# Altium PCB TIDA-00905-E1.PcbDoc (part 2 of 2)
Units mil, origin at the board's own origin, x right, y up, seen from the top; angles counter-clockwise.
Board outline 3740.15 x 5314.95 mil, 4 copper layers (Top Layer, GND, PWR, Bottom Layer), stack 79.834 mil thick; 196 components, 87 nets, 593 pads, 163 vias.
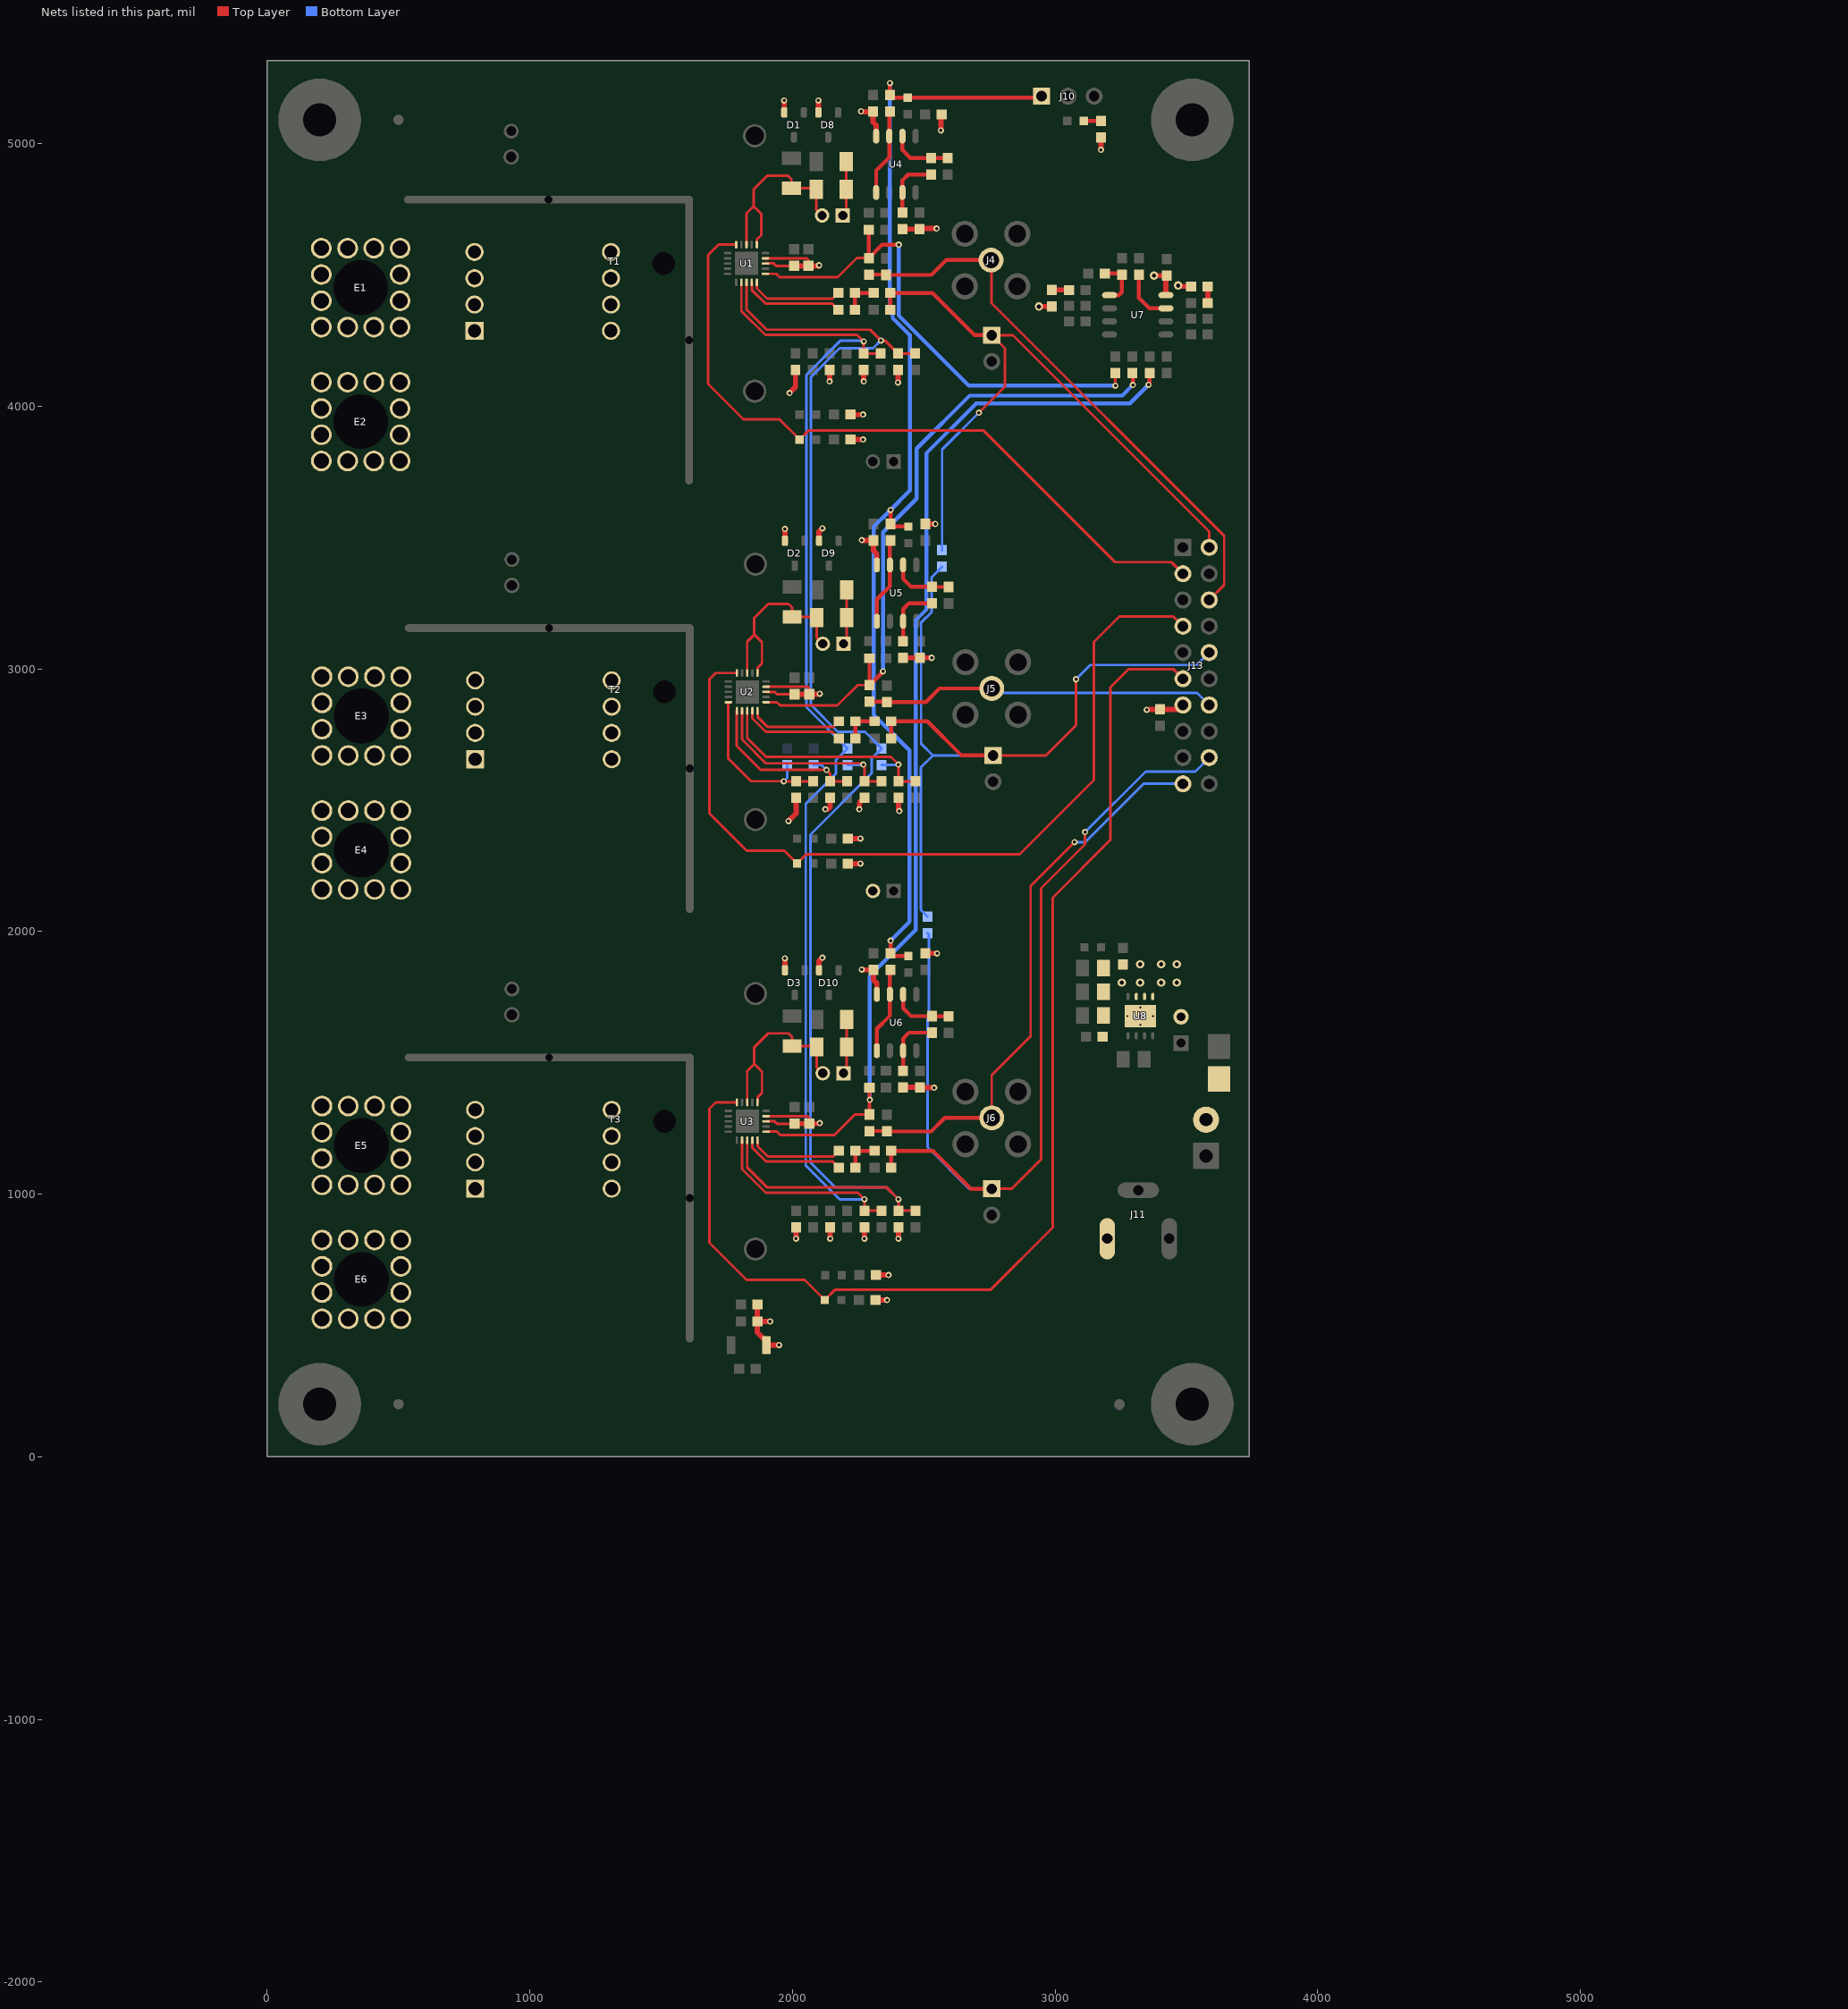
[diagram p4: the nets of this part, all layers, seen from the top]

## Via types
v1: diameter 24, hole 12, Top Layer to Bottom Layer, 127 vias
v2: diameter 32, hole 16, Top Layer to Bottom Layer, 19 vias
v3: diameter 19.68, hole 7.87, Top Layer to Bottom Layer, 17 vias

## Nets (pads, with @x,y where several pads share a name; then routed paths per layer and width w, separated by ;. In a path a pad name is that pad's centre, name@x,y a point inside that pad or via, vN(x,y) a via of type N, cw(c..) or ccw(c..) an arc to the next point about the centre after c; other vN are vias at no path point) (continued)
NetD17_2: D17.2 R82.1 | length 65.7
  Top Layer w15: D17.2@3109.5,5086 3110,5085.5 R82.1@3175,5085.5
NetD18_2: D18.2 J11.1 J14.2
NetE1_1: E1.1 T1.1 T1.2 T1.3 T1.4
NetE2_1: E2.1 T1.5 T1.6 T1.7 T1.8
NetE3_1: E3.1 T2.1 T2.2 T2.3 T2.4
NetE4_1: E4.1 T2.5 T2.6 T2.7 T2.8
NetE5_1: E5.1 T3.1 T3.2 T3.3 T3.4
NetE6_1: E6.1 T3.5 T3.6 T3.7 T3.8
NetJ1_1: J1.1 R12.2 R13.1 | length 210.3
  Top Layer w10: J1.1@2191.77,4726.11 2204.49,4738.83 R13.1@2204.49,4826.11 R12.2@2204.49,4931.11
NetJ1_2: J1.2 R3.2 R13.2 U1.11 U1.13 | length 797.9
  Top Layer w10: U1.13@1825.4,4614.96 1825.4,4734.11 1852.4,4761.11 ; U1.11@1864.77,4614.96 1864.77,4634.48 1881.4,4651.11 1881.4,4732.11 1852.4,4761.11 ; J1.2@2113.03,4726.11 2090.31,4748.83 R13.2@2090.31,4826.11 2087.4,4829.02 R3.2@1996.4,4829.02 1996.4,4864.11 1982.4,4878.11 1905.11,4878.11 1852.4,4825.4 1852.4,4761.11
NetJ2_1: J2.1 R14.2 R15.1 | length 210.3
  Top Layer w10: J2.1@2194.37,3095 2207.09,3107.72 R15.1@2207.09,3195 R14.2@2207.09,3300
NetJ2_2: J2.2 R4.2 R15.2 U2.11 U2.13 | length 797.9
  Top Layer w10: U2.13@1828,2983.85 1828,3103 1855,3130 ; U2.11@1867.37,2983.85 1867.37,3003.37 1884,3020 1884,3101 1855,3130 ; J2.2@2115.63,3095 2092.91,3117.72 R15.2@2092.91,3195 2090,3197.91 R4.2@1999,3197.91 1999,3233 1985,3247 1907.71,3247 1855,3194.29 1855,3130
NetJ3_1: J3.1 R16.2 R17.1 | length 210.3
  Top Layer w10: J3.1@2194.37,1460 2207.09,1472.72 R17.1@2207.09,1560 R16.2@2207.09,1665
NetJ3_2: J3.2 R5.2 R17.2 U3.11 U3.13 | length 797.9
  Top Layer w10: U3.13@1828,1348.85 1828,1468 1855,1495 ; U3.11@1867.37,1348.85 1867.37,1368.37 1884,1385 1884,1466 1855,1495 ; J3.2@2115.63,1460 2092.91,1482.72 R17.2@2092.91,1560 2090,1562.91 R5.2@1999,1562.91 1999,1598 1985,1612 1907.71,1612 1855,1559.29 1855,1495
NetR7_1: R7.1 R10.1 R91.2 U2.20 | length 640.2
  Top Layer w10: U2.20@1756.15,2872.63 1756.15,2657.85 1842.11,2571.89 v1@1966.6,2571.89 ; v1(1966.99,2571.5) R7.1@2014,2571.5 R10.1@2079,2571.5
  Bottom Layer w10: v1(1966.99,2571.5) 1980,2584.5 R91.2@1980,2633.5
NetR19_1: R19.1 R32.1 R90.2 U2.1 | length 685.6
  Top Layer w10: U2.1@1788.63,2840.15 1788.63,2705.37 1879,2615 v1(2130,2615) 2144,2601 R19.1@2144,2571.5 R32.1@2209,2571.5
  Bottom Layer w10: R90.2@2080,2633.5 2111.5,2633.5 v1(2130,2615)
NetR25_1: R25.1 U1.5 | length 360
  Top Layer w10: U1.5@1864.77,4471.26 1864.77,4448.2 1903.86,4409.11 2152.89,4409.11 R25.1@2174.89,4431.11 R25.1@2174.89,4429.6
NetR25_2: R25.2 R26.1 R45.1 | length 137
  Top Layer w15: R26.1@2237.9,4366.11 R25.2@2237.88,4431.11 R45.1@2309.91,4431.11
NetR26_2: R26.2 U1.4 | length 390.3
  Top Layer w10: U1.4@1845.09,4471.26 1845.09,4442.43 1896.4,4391.11 2149.91,4391.11 R26.2@2174.91,4366.11
NetR27_1: R27.1 U2.5 | length 360
  Top Layer w10: U2.5@1867.37,2840.15 1867.37,2817.09 1906.46,2778 2155.46,2778 R27.1@2177.46,2800 R27.1@2177.46,2798.49
NetR27_2: R27.2 R28.1 R46.1 | length 137
  Top Layer w15: R28.1@2240.47,2735 R27.2@2240.45,2800 R46.1@2312.48,2800
NetR28_2: R28.2 U2.4 | length 390.2
  Top Layer w10: U2.4@1847.68,2840.15 1847.68,2811.32 1899,2760 2152.48,2760 R28.2@2177.48,2735
NetR29_1: R29.1 U3.5 | length 360
  Top Layer w10: U3.5@1867.37,1205.15 1867.37,1182.09 1906.46,1143 2155.49,1143 R29.1@2177.49,1165 R29.1@2177.49,1163.49
NetR29_2: R29.2 R30.1 R47.1 | length 137
  Top Layer w15: R30.1@2240.5,1100 R29.2@2240.48,1165 R47.1@2312.5,1165
NetR30_2: R30.2 U3.4 | length 390.3
  Top Layer w10: U3.4@1847.68,1205.15 1847.68,1176.32 1899,1125 2152.5,1125 R30.2@2177.5,1100
NetR37_1: R37.1 R49.1 R89.2 U2.2 | length 810.3
  Top Layer w10: U2.2@1808.31,2840.15 1808.31,2730.69 1899,2640 v1@2270,2640 ; v1(2270,2635) v1@2270,2640 ; R49.1@2339,2571.5 R37.1@2274,2571.5 2274,2634 2275,2635 v1@2270,2640
  Bottom Layer w10: R89.2@2210,2633.5 2268.5,2633.5 v1(2270,2635)
NetR51_1: R51.1 U4.1 U4.7 | length 329.3
  Top Layer w15: U4.1@2319,4813.39 2319,4896.78 2369,4946.78 U4.7@2369,5027.95 2369,5118.5 R51.1@2371.48,5120.99
NetR52_1: R52.1 U5.1 U5.7 | length 329.3
  Top Layer w15: U5.1@2321.52,3180.91 2321.52,3264.3 2371.52,3314.3 U5.7@2371.52,3395.47 2371.52,3486.02 R52.1@2374,3488.5
NetR53_1: R53.1 U6.1 U6.7 | length 329.3
  Top Layer w15: U6.1@2321.52,1545.91 2321.52,1629.3 2371.52,1679.3 U6.7@2371.52,1760.47 2371.52,1851.02 R53.1@2374,1853.5
NetR55_1: R55.1 R61.1 R88.2 U2.3 | length 915.4
  Top Layer w10: U2.3@1828,2840.15 1828,2736.46 1899.46,2665 2375,2665 2404,2636 v1(2404,2635) R55.1@2404,2571.5 R61.1@2469,2571.5
  Bottom Layer w10: R88.2@2340,2633.5 2402.5,2633.5 v1(2404,2635)
NetR57_1: R57.1 R66.2 U4.3 | length 241.7
  Top Layer w15: R57.1@2419,4737.17 U4.3@2419,4813.39 2419,4860 2440.99,4881.99 R66.2@2528.75,4881.99
NetR58_1: R58.1 R67.2 U5.3 | length 241.7
  Top Layer w15: R58.1@2421.52,3104.69 U5.3@2421.52,3180.91 2421.52,3227.52 2443.51,3249.5 R67.2@2531.27,3249.5
NetR59_1: R59.1 R68.2 U6.3 | length 241.7
  Top Layer w15: R59.1@2421.52,1469.69 U6.3@2421.52,1545.91 2421.52,1592.52 2443.51,1614.5 R68.2@2531.27,1614.5
NetR66_1: R66.1 R69.2 U4.6 | length 238.3
  Top Layer w15: U4.6@2419,5027.95 2419,4974.96 2448.98,4944.98 R66.1@2528.75,4944.98 2529.75,4943.98 R69.2@2591.48,4943.98
NetR67_1: R67.1 R70.2 U5.6 | length 238.3
  Top Layer w15: U5.6@2421.52,3395.47 2421.52,3342.48 2451.5,3312.5 R67.1@2531.27,3312.5 2532.27,3311.5 R70.2@2594,3311.5
NetR68_1: R68.1 R71.2 U6.6 | length 238.3
  Top Layer w15: U6.6@2421.52,1760.47 2421.52,1707.48 2451.5,1677.5 R68.1@2531.27,1677.5 2532.27,1676.5 R71.2@2594,1676.5
NetR72_2: R72.2 R73.1 | length 65.8
  Top Layer w20: R72.2@2987.66,4442.5 R73.1@3053.47,4442.48
NetR75_2: R75.2 R78.1 U7.1 | length 189.4
  Top Layer w15: R75.2@3184.43,4499.98 R75.2@3189.16,4499.98 ; R75.2@3189.16,4505 3249.41,4505 R78.1@3254.43,4499.98 3254.43,4434.24 3242.66,4422.48 U7.1@3207.68,4422.48
NetR80_1: R80.1 U7.7 | length 207
  Top Layer w15: R80.1@3319.43,4499.98 3319.43,4412.24 3359.18,4372.48 U7.7@3422.25,4372.48
NetR83_2: R83.2 R84.1 | length 63.6
  Top Layer w20: R84.1@3581.46,4392.48 R83.2@3581.5,4456
OC_FAULT: D13.1 D14.1 D15.1 J10.1 R51.2 R52.2 R53.2 | length 4314.5
  Top Layer w15: v1(2371.48,5230) R51.2@2371.48,5183.98 2381.48,5173.98 D13.1@2438.92,5173.98 2942.98,5173.98 J10.1@2949,5180 ; v1(2374,1965) R53.2@2374,1916.5 2384,1906.5 D15.1@2441.44,1906.5 ; v1(2374,3605) R52.2@2374,3551.5 2384,3541.5 D14.1@2441.44,3541.5
  Bottom Layer w15: v1(2371.48,5230) 2371.48,4358 2382,4347.48 2382,4335.47 2447,4270.47 2447,3678 v1(2374,3605) 2310,3541 2310,2825 2446,2689 2446,2037 v1(2374,1965)
OR-U: D11.1 J13.11 U3.15 | length 4604.6
  Top Layer w10: U3.15@1788.63,1348.85 1707.85,1348.85 1684,1325 1684,815 1825.54,673.46 2046.53,673.46 D11.1@2123.53,596.46 2163.53,636.46 2755.46,636.46 2991,872 2991,2129 3211,2349 3211,2929 3281,2999 3450,2999 J13.11@3487,2962
OR-V: D5.1 J13.7 U2.15 | length 3219.8
  Top Layer w10: U2.15@1788.63,2983.85 1707.85,2983.85 1684,2960 1684,2449.54 1826.54,2307 1969.05,2307 D5.1@2017.5,2258.54 2052.5,2293.54 2865,2293.54 3148,2576.54 3148,3102 3245,3199 3450,3199 J13.7@3487,3162
OR-W: D7.1 J13.3 U1.15 | length 2750.3
  Top Layer w10: U1.15@1786.03,4614.96 1718.96,4614.96 1679,4575 1679,4084.54 1813.81,3949.73 1950.48,3949.73 D7.1@2027.48,3872.73 2062.48,3907.73 2726.81,3907.73 3228.54,3406 3443,3406 J13.3@3487,3362
REFOUT-U: C16.1 J8.1 J13.18 R47.2 R87.1 | length 3776.9
  Top Layer w10: J8.1@2759,1020 2835,1020 2947,1132 2947,2164 3114,2331 v1(3114,2378)
  Top Layer w15: C16.1@2375.5,1100 R47.2@2375.5,1165 2535,1165 2680,1020 J8.1@2759,1020
  Bottom Layer w10: R87.1@2515,1993.5 2519.52,1988.98 2519.52,1686.64 2515,1682.12 2515,1179 2674,1020 J8.1@2759,1020 ; v1(3114,2378) 3345,2609 3534,2609 J13.18@3587,2662
REFOUT-V: C15.1 J9.1 J13.10 R46.2 R86.1 R87.2 | length 3237.5
  Top Layer w10: J9.1@2764,2670 2965,2670 3080,2785 v1(3080,2960)
  Top Layer w15: C15.1@2375.47,2735 R46.2@2375.47,2800 2514,2800 2644,2670 J9.1@2764,2670
  Bottom Layer w10: R87.2@2515,2056.5 2489.5,2082 2489.5,2624.5 2535,2670 ; R86.1@2570,3388.5 2530.5,3349 2530.5,3216.51 2490,3176.01 2490,2715 2535,2670 ; J9.1@2764,2670 2535,2670 ; v1(3080,2960) 3134.52,3014.52 3539.52,3014.52 J13.10@3587,3062
REFOUT-W: C12.1 J7.1 J13.2 R45.2 R86.2 | length 2654.5
  Top Layer w10: v1(2710,3975) 2809,4074 2809,4220 J7.1@2759,4270 2840,4270 3587,3523 J13.2@3587,3462
  Top Layer w15: C12.1@2372.9,4366.11 R45.2@2372.9,4431.11 2532.89,4431.11 2694,4270 J7.1@2759,4270
  Bottom Layer w10: R86.2@2570,3451.5 2570,3835 v1(2710,3975)
RSEL0: R54.1 R56.1 R60.1 R62.1 R88.1 U1.3 U3.3 | length 5644.7
  Top Layer w10: U1.3@1825.4,4471.26 1825.4,4367.57 1901.86,4291.11 2295.89,4291.11 v1(2337,4250) 2352.23,4250 R54.1@2401.73,4200.5 R60.1@2466.73,4200.5 ; U3.3@1828,1205.15 1828,1101.46 1904.46,1025 2359,1025 v1(2404,980) R56.1@2404,936.5 R62.1@2469,936.5
  Bottom Layer w10: v1(2337,4250) 2307,4220 2179.46,4220 2071,4111.54 2071,2861.98 2172.98,2760 2276.5,2760 R88.1@2340,2696.5 2301.27,2657.76 2301.27,2601.27 2069,2369 2069,1120.46 2164.46,1025 2359,1025 v1(2404,980)
RSEL1: R36.1 R38.1 R48.1 R50.1 R89.1 U1.2 U3.2 | length 5158.7
  Top Layer w10: U1.2@1805.72,4471.26 1805.72,4361.8 1896.4,4271.11 2246.4,4271.11 v1(2271.4,4246.11) R36.1@2271.4,4202.61 ; U3.2@1808.31,1205.15 1808.31,1095.69 1899,1005 2249,1005 v1(2274,980) R38.1@2274,936.5 ; R36.1@2270.24,4200.5 R36.1@2271.73,4200.5 R48.1@2336.73,4200.5 ; R38.1@2272.5,936.5 R38.1@2274,936.5 ; R50.1@2339,936.5 R38.1@2274,936.5
  Bottom Layer w10: v1(2274,980) 2180,980 2051,1109 2051,2486 2166,2601 2166,2652.5 R89.1@2210,2696.5 2053,2853.5 2053,4119 2184,4250 v1@2274,4250
VDD: C1.1 C2.1 C3.1 C4.1 C5.1 C6.1 C7.1 C11.1 C13.1 C14.1 C20.1 C21.1 C22.1 C24.2 C25.1 C26.1 C27.1 C28.2 C30.1 D1.2 D2.2 D3.2 D8.2 D9.2 D10.2 J12.2 J13.13 J15.2 R2.2 R6.2 R7.2 R8.2 R18.2 R19.2 R20.2 R21.2 R22.2 R23.2 R24.2 R34.2 R35.2 R36.2 R37.2 R38.2 R54.2 R55.2 R56.2 R57.2 R58.2 R59.2 R63.2 R64.2 R65.2 R72.1 R76.2 R82.2 R83.1 S1.1 U1.8 U1.9 U2.8 U2.9 U3.8 U3.9 U4.8 U5.8 U6.8 U7.8 U8.5 U8.6 U8.7 U8.9 | length 4047.4
  Top Layer w10: U1.8@1897.25,4543.11 1929.4,4543.11 1938.45,4534.06 C2.1@2006.4,4534.06 ; U1.9@1897.25,4562.8 2055,4562.8 2061,4556.8 2061,4534.46 C5.1@2061.4,4534.06 ; U3.8@1899.85,1277 1932,1277 1941.05,1267.95 C4.1@2009,1267.95 ; U3.9@1899.85,1296.69 2057.6,1296.69 2063.6,1290.69 2063.6,1268.35 C7.1@2064,1267.95 ; U2.8@1899.85,2912 1932,2912 1941.05,2902.95 C3.1@2009,2902.95 ; U2.9@1899.85,2931.69 2057.6,2931.69 2063.6,2925.69 2063.6,2903.35 C6.1@2064,2902.95
  Top Layer w20: R2.2@1866.5,580 C1.1@1866.5,515 ; v1(1915,515) C1.1@1866.5,515 ; v1(1949.43,425) S1.1@1900.93,425 1900.93,439.07 1866.5,473.5 C1.1@1866.5,515 ; D1.2@1969,5118.35 v1(1969,5163.51) ; D3.2@1971.6,1852.24 v1(1971.6,1897.4) ; D2.2@1971.6,3487.24 v1(1971.6,3532.4) ; v1(1985,2420) 2014,2449 R7.2@2014,2508.5 ; v1(1989,4050) 2011.73,4072.73 R6.2@2011.73,4137.5 ; C2.1@2006.4,4534.06 C5.1@2061.4,4534.06 2099.36,4534.06 v1(2101.4,4536.11) ; C4.1@2009,1267.95 C7.1@2064,1267.95 2101.95,1267.95 v1(2104,1270) ; C3.1@2009,2902.95 C6.1@2064,2902.95 2101.95,2902.95 v1(2104,2905) ; v1(2014,830) R8.2@2014,873.5 ; D8.2@2099,5118.35 v1(2099,5163.51) ; D10.2@2101.6,1852.24 2101.6,1887.6 v1(2114,1900) ; D9.2@2101.6,3487.24 2101.6,3522.6 v1(2114,3535) ; v1(2125,2465) 2135,2465 2144,2474 R19.2@2144,2508.5 ; v1(2141.73,4094) R18.2@2141.73,4137.5 ; v1(2144,830) R20.2@2144,873.5 ; R22.2@2210.5,2258.54 v1(2259,2258.54) ; R21.2@2210.5,2353.54 v1(2259,2353.54) ; R24.2@2220.47,3872.73 v1(2268.98,3872.73) ; R23.2@2220.47,3967.73 v1(2268.98,3967.73) ; v1(2255,2465) 2255,2490 ; R37.2@2255.5,2490 R37.2@2274,2508.5 ; v1(2261.48,5122.48) 2262.98,5120.99 C11.1@2306.48,5120.99 2306.48,5082.48 2319,5069.96 U4.8@2319,5027.95 ; v1(2264,1855) 2265.5,1853.5 C14.1@2309,1853.5 2309,1815 2321.52,1802.48 U6.8@2321.52,1760.47 ; v1(2264,3490) 2265.5,3488.5 C13.1@2309,3488.5 2309,3450 2321.52,3437.48 U5.8@2321.52,3395.47 ; v1(2271.73,4094) R36.2@2271.73,4137.5 ; v1(2274,830) R38.2@2274,873.5 ; R34.2@2316.52,596.46 v1(2360.02,596.46) ; R35.2@2318.02,691.46 v1(2366.52,691.46) ; v1(2401.73,4090) R54.2@2401.73,4137.5 ; v1(2404,830) R56.2@2404,873.5 ; R55.2@2404,2508.5 2404,2461 v1(2407,2458) ; R57.2@2419,4674.17 C20.1@2484,4674.17 2486.2,4676.37 v1(2549.08,4676.37) ; R59.2@2421.52,1406.69 C22.1@2486.52,1406.69 2488.21,1405 v1(2540,1405) ; R58.2@2421.52,3041.69 C21.1@2486.52,3041.69 v1(2530.69,3041.69) ; R65.2@2506.44,1916.5 v1(2550.5,1916.5) ; R64.2@2506.44,3551.5 v1(2544,3551.5) ; v1(2565.37,5049.92) 2565.37,5107.47 R63.2@2567.98,5110.08 ; v2@2939.17,4379.5 R72.1@2987.66,4379.5 ; v1(3175,4976.01) R82.2@3175,5022.5 ; v1(3349,2844) 3350.5,2845.5 C30.1@3399,2845.5 3470.5,2845.5 J13.13@3487,2862 ; v2(3376.5,4497.17) C24.2@3424,4497.17 ; U7.8@3422.77,4423 U7.8@3422.25,4422.48 3422.25,4494.42 C24.2@3425,4497.16 ; v2(3469,4459) 3472,4456 R83.1@3518.5,4456
  other v2: 3254,1805 3324,1805 3404,1805 3464,1805 3324,1875 3404,1875 3464,1875 2938.66,4379
  other v3: 3324.71,1644.09 3275.5,1677.56 3324.71,1677.56 3373.92,1677.56 3324.71,1711.02
VO-U: R42.1 R44.1 R81.1 U3.6 | length 4075
  Top Layer w10: U3.6@1899.85,1237.63 1941.37,1237.63 1954,1225 2160,1225 2237.95,1302.95 R44.1@2294,1302.95
  Top Layer w15: R44.1@2293.5,1303.45 R44.1@2294,1302.95 ; R44.1@2293.5,1313.45 R42.1@2293.5,1405 ; v1(3356.18,4081.52) 3359.97,4085.31 R81.1@3359.97,4125.98
  Bottom Layer w15: v1(2294.5,1358.77) 2294.5,1830.5 2469,2005 2469,3184 2510,3225 2510,3820 2700,4010 3284.66,4010 v1(3356.18,4081.52)
VO-V: R41.1 R43.1 R79.1 U2.6 | length 2477.8
  Top Layer w10: U2.6@1899.85,2872.63 1941.37,2872.63 1954,2860 2170.99,2860 2248.95,2937.95 R43.1@2294,2937.95
  Top Layer w15: R41.1@2293.5,3040 2293.5,2938.45 R43.1@2294,2937.95 2345,2988.95 v1(2345,2990) ; R79.1@3294.97,4125.98 3296.18,4124.77 v1(3296.18,4080.45)
  Bottom Layer w15: v1(2345,2990) 2345,3519.54 2473,3647.54 2473,3838 2675,4040 3255.73,4040 v1(3296.18,4080.45)
VO-W: R39.1 R40.1 R77.1 U1.6 | length 1923.5
  Top Layer w10: U1.6@1897.25,4503.74 1938.77,4503.74 1951.4,4491.11 2172.4,4491.11 2245.35,4564.06 R40.1@2291.4,4564.06 ; v1(3229.97,4077.69) R77.1@3229.97,4125.98
  Top Layer w15: R39.1@2290.91,4669.09 2291.4,4668.6 R40.1@2291.4,4564.06 2342.34,4615 v1(2405,4615)
  Bottom Layer w15: v1(2405,4615) 2405,4345 2672.31,4077.69 v1(3229.97,4077.69)
VOUT-U: C19.1 J6.1 J13.19 R44.2 | length 2172.4
  Top Layer w10: C19.1@2357.54,1239.96 C19.1@2359,1238.5 ; J6.1@2759,1290 2759,1453 2907,1601 2907,2173 v1(3074,2340)
  Top Layer w15: R44.2@2294,1239.96 C19.1@2357.54,1239.96 ; C19.1@2359,1238.5 2528.5,1238.5 2580,1290 J6.1@2759,1290
  Bottom Layer w10: v1(3074,2340) 3115,2340 3337,2562 J13.19@3487,2562
VOUT-V: C18.1 J5.1 J13.14 R43.2 | length 1351
  Top Layer w10: C18.1@2357.54,2874.96 C18.1@2359,2873.5
  Top Layer w15: R43.2@2294,2874.96 C18.1@2357.54,2874.96 ; C18.1@2359,2873.5 2508.5,2873.5 2560,2925 J5.1@2759,2925
  Bottom Layer w10: J5.1@2759,2925 2759,2908 3541,2908 J13.14@3587,2862
VOUT-W: C17.1 J4.1 J13.6 R40.2 | length 2175.3
  Top Layer w10: C17.1@2354.94,4501.07 C17.1@2356.4,4499.61 ; J4.1@2757.9,4556.11 2757.9,4392.1 3644,3506 3644,3319 J13.6@3587,3262
  Top Layer w15: R40.2@2291.4,4501.07 C17.1@2354.94,4501.07 ; C17.1@2356.4,4499.61 2529.61,4499.61 2586.11,4556.11 J4.1@2756.4,4556.11 J4.1@2757.9,4556.11
pads on no net: E1. E2. E3. E4. E5. E6. FID1.1 FID2.1 FID3.1 FID4.1 FID5.1 FID6.1 H1.1 H2.1 H3.1 H4.1 H5.0 H6.0 H7.0 H8.0 J16.1 J16.2 LBL1.0 T1.MH1 T1.MH2 T1.MH3 T2.MH1 T2.MH2 T2.MH3 T3.MH1 T3.MH2 T3.MH3 U8.8

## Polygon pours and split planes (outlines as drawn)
NetE5_1 on Top Layer "Top Layer-No Net 1" (solid, remove dead copper, pour order 50): 864,1390 879,1375 879,955 869,945 719,945 89,945 49,985 49,1365 74,1390
NetE6_1 on Top Layer "Top Layer-No Net 1" (solid, remove dead copper, pour order 62): 504,890 89,890 64,865 49,850 49,730 49,460 64,445 1349,445 1359,455 1359,1380 1349,1390 949,1390 934,1375 934,905 919,890
NetE4_1 on Top Layer "Top Layer-No Net 1" (solid, remove dead copper, pour order 58): 504,2525 89,2525 64,2500 49,2485 49,2365 49,2095 64,2080 1349,2080 1359,2090 1359,3015 1349,3025 949,3025 934,3010 934,2540 919,2525
NetE2_1 on Top Layer "Top Layer-No Net 1" (solid, remove dead copper, pour order 54): 501.4,4156.11 86.4,4156.11 61.4,4131.11 46.4,4116.11 46.4,3996.11 46.4,3726.11 61.4,3711.11 1346.4,3711.11 1356.4,3721.11 1356.4,4646.11 1346.4,4656.11 946.4,4656.11 931.4,4641.11 931.4,4171.11 916.4,4156.11
NetE1_1 on Top Layer "Top Layer-No Net 1" (solid, remove dead copper, pour order 44): 861.4,4656.11 876.4,4641.11 876.4,4221.11 866.4,4211.11 716.4,4211.11 86.4,4211.11 46.4,4251.11 46.4,4631.11 71.4,4656.11
NetE3_1 on Top Layer "Top Layer-No Net 1" (solid, remove dead copper, pour order 47): 864,3025 879,3010 879,2590 869,2580 719,2580 89,2580 49,2620 49,3000 74,3025
GND on Top Layer "Top Layer-No Net 1" (solid, remove dead copper, pour order 66): 3129,1895 3129,1635 3129,1555 3139,1545 3289,1545 3289,1211 3300,1200 3634,1200 3644,1190 3644,710 3614,680 3389,680 3379,690 3379,925 3379,960 3369,970 3059,970 3034,970 3014,990 3014,1975 3024,1985 3124,1985 3129,1980
VDD on Top Layer "Top Layer-No Net 1" (solid, remove dead copper, pour order 65): 3164,1900 3514,1900 3519,1895 3519,1650 3509,1640 3504,1635 3364,1635 3216.72,1635 3208.98,1627.27 3208.98,1577.78 3204,1572.8 3156.2,1572.8 3154,1575 3154,1675 3154,1895 3159,1900
NetC29_1 on Top Layer "Top Layer-No Net 1" (solid, remove dead copper, pour order 63): 3304,1615 3675,1615 3680,1610 3680,1520 3675,1515 3429,1515 3384,1470 3309,1470 3304,1475
NetD18_2 on Top Layer "Top Layer-No Net 1" (solid, remove dead copper, pour order 37): 3580,1490 3665,1490 3670,1485 3670,1245 3655,1230 3530,1230 3520,1240 3520,1485 3525,1490
GND on Top Layer "Top Layer-No Net 1" (solid, remove dead copper, pour order 36): 3261,1617 3283,1617 3287,1613 3289,1611 3289,1531 3289,1513 3277,1501 3243,1501 3237,1507 3237,1543 3247,1553 3247,1612 3252,1617
NetD18_2 on Bottom Layer "Top Layer-No Net 1" (solid, remove dead copper, pour order 64): 3189,915 3229,915 3239,905 3239,750 3224,735 3084,735 3074,745 3074,1300 3084,1310 3114,1340 3650,1340 3670,1320 3670,1245 3655,1230 3169,1230 3169,1120 3169,925 3179,915
NetE1_1 on Bottom Layer "Top Layer-No Net 1" (solid, remove dead copper, pour order 34): 861.4,4656.11 876.4,4641.11 876.4,4221.11 866.4,4211.11 716.4,4211.11 86.4,4211.11 46.4,4251.11 46.4,4631.11 71.4,4656.11
NetE3_1 on Bottom Layer "Top Layer-No Net 1" (solid, remove dead copper, pour order 35): 864,3025 879,3010 879,2590 869,2580 719,2580 89,2580 49,2620 49,3000 74,3025
NetE5_1 on Bottom Layer "Top Layer-No Net 1" (solid, remove dead copper, pour order 38): 864,1390 879,1375 879,955 869,945 719,945 89,945 49,985 49,1365 74,1390
NetE6_1 on Bottom Layer "Top Layer-No Net 1" (solid, remove dead copper, pour order 59): 504,890 89,890 64,865 49,850 49,730 49,460 64,445 1349,445 1359,455 1359,1380 1349,1390 949,1390 934,1375 934,905 919,890
NetE4_1 on Bottom Layer "Top Layer-No Net 1" (solid, remove dead copper, pour order 55): 504,2525 89,2525 64,2500 49,2485 49,2365 49,2095 64,2080 1349,2080 1359,2090 1359,3015 1349,3025 949,3025 934,3010 934,2540 919,2525
NetE2_1 on Bottom Layer "Top Layer-No Net 1" (solid, remove dead copper, pour order 51): 501.4,4156.11 86.4,4156.11 61.4,4131.11 46.4,4116.11 46.4,3996.11 46.4,3726.11 61.4,3711.11 1346.4,3711.11 1356.4,3721.11 1356.4,4646.11 1346.4,4656.11 946.4,4656.11 931.4,4641.11 931.4,4171.11 916.4,4156.11
GND on Bottom Layer "Top Layer-No Net 1" (solid, remove dead copper, pour order 41): 1674,4570 1674,5250 1679,5255 3694,5255 3699,5250 3699,40 3694,35 1684,35 1674,45
NetE6_1 on GND "Top Layer-No Net 1" (solid, remove dead copper, pour order 61): 504,890 89,890 64,865 49,850 49,730 49,460 64,445 1349,445 1359,455 1359,1380 1349,1390 949,1390 934,1375 934,905 919,890
NetE5_1 on GND "Top Layer-No Net 1" (solid, remove dead copper, pour order 49): 864,1390 879,1375 879,955 869,945 719,945 89,945 49,985 49,1365 74,1390
NetE4_1 on GND "Top Layer-No Net 1" (solid, remove dead copper, pour order 57): 504,2525 89,2525 64,2500 49,2485 49,2365 49,2095 64,2080 1349,2080 1359,2090 1359,3015 1349,3025 949,3025 934,3010 934,2540 919,2525
NetE3_1 on GND "Top Layer-No Net 1" (solid, remove dead copper, pour order 46): 864,3025 879,3010 879,2590 869,2580 719,2580 89,2580 49,2620 49,3000 74,3025
NetE2_1 on GND "Top Layer-No Net 1" (solid, remove dead copper, pour order 53): 501.4,4156.11 86.4,4156.11 61.4,4131.11 46.4,4116.11 46.4,3996.11 46.4,3726.11 61.4,3711.11 1346.4,3711.11 1356.4,3721.11 1356.4,4646.11 1346.4,4656.11 946.4,4656.11 931.4,4641.11 931.4,4171.11 916.4,4156.11
NetE1_1 on GND "Top Layer-No Net 1" (solid, remove dead copper, pour order 43): 861.4,4656.11 876.4,4641.11 876.4,4221.11 866.4,4211.11 716.4,4211.11 86.4,4211.11 46.4,4251.11 46.4,4631.11 71.4,4656.11
GND on GND "Top Layer-No Net 1" (solid, remove dead copper, pour order 40): 1674,4570 1674,5250 1679,5255 3694,5255 3699,5250 3699,40 3694,35 1684,35 1674,45
NetE6_1 on PWR "Top Layer-No Net 1" (solid, remove dead copper, pour order 60): 504,890 89,890 64,865 49,850 49,730 49,460 64,445 1349,445 1359,455 1359,1380 1349,1390 949,1390 934,1375 934,905 919,890
NetE5_1 on PWR "Top Layer-No Net 1" (solid, remove dead copper, pour order 48): 864,1390 879,1375 879,955 869,945 719,945 89,945 49,985 49,1365 74,1390
NetE4_1 on PWR "Top Layer-No Net 1" (solid, remove dead copper, pour order 56): 504,2525 89,2525 64,2500 49,2485 49,2365 49,2095 64,2080 1349,2080 1359,2090 1359,3015 1349,3025 949,3025 934,3010 934,2540 919,2525
NetE3_1 on PWR "Top Layer-No Net 1" (solid, remove dead copper, pour order 45): 864,3025 879,3010 879,2590 869,2580 719,2580 89,2580 49,2620 49,3000 74,3025
NetE2_1 on PWR "Top Layer-No Net 1" (solid, remove dead copper, pour order 52): 501.4,4156.11 86.4,4156.11 61.4,4131.11 46.4,4116.11 46.4,3996.11 46.4,3726.11 61.4,3711.11 1346.4,3711.11 1356.4,3721.11 1356.4,4646.11 1346.4,4656.11 946.4,4656.11 931.4,4641.11 931.4,4171.11 916.4,4156.11
NetE1_1 on PWR "Top Layer-No Net 1" (solid, remove dead copper, pour order 42): 861.4,4656.11 876.4,4641.11 876.4,4221.11 866.4,4211.11 716.4,4211.11 86.4,4211.11 46.4,4251.11 46.4,4631.11 71.4,4656.11
VDD on PWR "Top Layer-No Net 1" (solid, remove dead copper, pour order 39): 1674,4570 1674,5250 1679,5255 3694,5255 3699,5250 3699,40 3694,35 1684,35 1674,45

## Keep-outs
Keep-Out Layer:
  lines w10: 20,20 3715,20 3715,2586 3715,3765 3715,5295 20,5295 20,20
  text ".Layer_Name" at 137,-1614.49 h60

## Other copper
Top Layer:
  text ".layer_Name" at 152,-1604 h60
GND:
  text "GND" at 220,-1600 h60
PWR:
  text "PWR" at 230,-1600 h60
Bottom Layer:
  text ".Layer_Name" at 211,-1614 h60
Multi-Layer:
  pour cut-out: 1677.6,2293.89 1939.6,2293.89 1939.6,1898.89 1677.71,1898.89
  pour cut-out: 1675,3925 1937,3925 1937,3530 1675.11,3530

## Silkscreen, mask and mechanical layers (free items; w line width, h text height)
Top Overlay:
  lines w6: 2040,4755 2040,4765.56 2052.91,4778.47 ; 2045.02,1495 2056,1505.98 ; 2050,3130 2050,3140 2055.51,3145.51 2055.51,3147.36 ; 2265.02,3132.2 2265.02,3149.98 ; 2270,4765 2270,4790 ; 2275,1505 2275,1515 ; 2285,2455 2285,2470 ; 2339,4242 2339,4248 ; 2346.5,664.26 2346.5,663.5 2360,650 ; 2385,2450 2385,2470 ; 2395,2900 2415,2900 ; 2400,1255 2415,1255 ; 2435,4645 2435,4620 2455,4600 ; 2500,4645 2500,4636.97 2506,4630.97 ; 3001.66,4291 3008.66,4291 3012.94,4295.28 3024.99,4295.28 ; 3050.66,4485 3050.66,4520 ; 3354,1782 3354,1787 3364,1797 3364,1811 ; 3472.66,4391 3472.66,4224 3553.66,4224 ; 3487.34,4499.34 3487.34,4516.34 3528.66,4516.34 3528.66,4549 3528.66,4731 3565.66,4731 3632.66,4731 3632.66,4452.66 3622,4442 3622,4435 3621,4434 ; 3597.66,4499 3597.66,4540 ; 3606.66,4222 3621,4222 ; 3621,4223.34 3621,4290 ; 3050.66,4520 3052.66,4520 3058.66,4514 3044.66,4514 3050.66,4520 ; 3597.66,4540 3598.66,4540 3606.66,4532 3589.66,4532 3597.66,4540
  lines w10: -732,-1686.17 5868,-1686.17 ; -732,-1482.83 5870,-1482.83 ; -732,-1279.5 -732,-1889.5 3273,-1889.5 5870,-1889.5 5870,-1279.5 -731.5,-1279.5 -731.5,-1889.5 ; 1733,-1889.5 1733,-1279.5 ; 3000,-1482.83 3000,-1279.5 ; 3172.66,4210 3172.66,4225 3192.66,4245 ; 3840,-1482.83 3840,-1279.5 ; 4462,-1896 4462,-1693.17 ; 179.24,3763.94 179.24,4118.28 533.57,4118.28 533.57,3763.94 179.24,3763.94 ; 179.24,4273.95 179.24,4628.28 533.57,4628.28 533.57,4273.95 179.24,4273.95 ; 181.84,497.83 181.84,852.17 536.17,852.17 536.17,497.83 181.84,497.83 ; 181.84,1007.84 536.17,1007.84 536.17,1362.17 181.84,1362.17 181.84,1007.84 ; 181.84,2132.83 181.84,2487.17 536.17,2487.17 536.17,2132.83 181.84,2132.83 ; 181.84,2642.84 181.84,2997.17 536.17,2997.17 536.17,2642.84 181.84,2642.84
  text "VIN" at 3373,1264 h30
  text "GND" at 3367,1113 h30
  text "TIDA-00905-E1" at 2197.55,91.37 h60
  text ".layer_Name" at 178,-1602 h60
Bottom Overlay:
  text ".Layer_Name" at 137,-1614.49 h60
Top Paste:
  text ".Layer_Name" at 125,-1617.49 h60
Bottom Paste:
  text ".Layer_Name" at 125,-1617.49 h60
Top Solder:
  text ".Layer_Name" at 153,-1625 h60
Bottom Solder:
  text ".Layer_Name" at 200,-1621 h60
M1 Board Outline:
  the board outline again, w10
M2 Board Dimensions:
  rectangle: -610.5,-891 -485.5,-766
  rectangle: -485.5,-1016 -110.5,-891
  lines w7: -610.5,-891 389.5,-891 ; -485.5,-1016 -485.5,-766 ; -360.5,-1016 -360.5,-766 ; -110.5,-1016 -110.5,-766 ; 139.5,-1016 139.5,-766 ; -610.5,-1016 389.5,-1016 389.5,-766 -610.5,-766 -610.5,-1016
M3 3D STEP Top:
  text ".Layer_Name" at 137,-1614.49 h60
M4 3D STEP Bottom:
  text ".Layer_Name" at 137,-1614.49 h60
M5 Assembly Top:
  circle w10: c3474.27,1568.64 r11.18
  circle w10: c2189.27,4728.64 r11.18
  circle w10: c2199.27,1459.27 r11.18
  circle w10: c2195,3090 r11.18
  circle w10: c2147.4,5141.11 r10.28
  circle w10: c2022.4,3510 r13.06
  circle w10: c2150,3510 r10.28
  circle w10: c2150,1875 r10.28
  circle w10: c2022.4,1875 r13.06
  circle w10: c2388,3792 r10.77
  circle w10: c2387,2154 r13.6
  lines w6: -732,-1482 5872,-1482 ; -730.5,-1686 5874,-1686 ; 1734,-1887 1734,-1279.5 ; 2138,-1482 2138,-1279.5 ; 3000,-1480.33 3000,-1280 ; 3405,-1887 3405,-1279.5 ; 3842,-1478 3842,-1279 ; -731,-1888 5874,-1888 5874,-1282 5871.5,-1279.5 -731,-1279.5 -731,-1888
  text "COMPONENTS MARKED 'DNP' SHOULD NOT BE POPULATED." at 713.5,-1074.5 h30
  text "ASSEMBLY VARIANT:" at 713,-1190 h30
  text ".VariantName" at 1749,-1190 h30
  text "ALL ARTWORK VIEWED FROM TOP SIDE" at -668.5,-1411.67 h30
  text "BOARD #:" at 1808,-1411.67 h30
  text ".PRJ_Number" at 2353.5,-1411.67 h30
  text "REV:" at 3198,-1411.67 h30
  text ".PCB_Rev" at 3489.5,-1411.67 h30
  text "SVN REV:" at 4036,-1411.67 h30
  text ".VersionControl_RevNumber" at 4542,-1411.67 h30
  text ".layer_Name" at 95,-1594 h30
  text "LAYER NAME =" at -675,-1601 h30
  text ".plot_File_Name" at -677,-1790 h30
  text "GENERATED    :" at 1810,-1820.34 h30
  text ".Print_Date" at 2679.5,-1820.34 h30
  text ".Print_Time" at 3408.5,-1820.34 h30
  text "TEXAS INSTRUMENTS" at 4673,-1820.34 h30
M6 Assembly Bottom:
  lines w6: -732.5,-1483.33 5869.5,-1483.33 ; -730.5,-1686.67 5869.5,-1686.67 ; 1297.5,-1483.33 1297.5,-1280 ; 2137.5,-1483.33 2137.5,-1280 ; 3404.5,-1890 3404.5,-1280 ; 4293.5,-1890 5869,-1890 5869,-1280 -732.5,-1280 -732.5,-1890 1864.5,-1890 5869.5,-1890 5869.5,-1280
  text "COMPONENTS MARKED 'DNP' SHOULD NOT BE POPULATED." at 5662,-1074 h30
  text ".VariantName" at 4618,-1190 h30
  text "ASSEMBLY VARIANT:" at 5657,-1190 h30
  text "SVN REV:" at 1101.5,-1412.17 h30
  text ".PCB_Rev" at 1648,-1412.17 h30
  text "REV:" at 1939.5,-1412.17 h30
  text ".PRJ_Number" at 2784,-1412.17 h30
  text "BOARD #:" at 3329.5,-1412.17 h30
  text "PCB VIEWED FROM BOTTOM SIDE" at 5806,-1412.17 h30
  text "LAYER NAME =" at 5801,-1597 h30
  text ".Layer_Name" at 5028,-1604 h30
  text "IGNORE ->" at 2107.85,-1614.49 h30
  text ".Print_Time" at 1729,-1820.84 h30
  text ".Print_Date" at 2458,-1820.84 h30
  text "GENERATED    :" at 3327.5,-1820.84 h30
  text ".plot_File_Name" at 5000.5,-1820.84 h30
  text "PLOT NAME =" at 5806,-1820.84 h30
M9 Title Sheet:
  drawing of 57 lines, arcs and shapes, not listed
  text "1" at 299.84,7280.5 h70
  text "2" at 2795.5,7280.5 h70
  text "3" at 5284.84,7280.5 h70
  text "4" at 7791.51,7280.5 h70
  text "5" at 10290.5,7280.5 h70
  text "6" at 12795.5,7280.5 h70
  text "A" at -856.5,6137.5 h70
  text "A" at 13943.5,6137.5 h70
  text "B" at -856.5,3757.5 h70
  text "B" at 13943.5,3757.5 h70
  text "C" at -856.5,1382.5 h70
  text "C" at 13943.5,1382.5 h70
  text "PROJECT TITLE:" at 10903.5,-478.5 h45
  text ".PRJ_Title" at 11405,-605 h70
  text "DESIGNED FOR:" at 10903.5,-779.5 h45
  text ".PRJ_Customer" at 10953.5,-919.5 h70
  text "D" at -856.5,-987.5 h70
  text "D" at 13943.5,-987.5 h70
  text "FILE NAME:" at 10903.5,-1079.5 h45
  text ".PCB_File_Name_No_Path" at 11235,-1205 h70
  text "Texas Instruments (TI) and/or its licensors do not warrant the accuracy or completeness of this specification" at 5934,-1361.34 h45
  text "ENGINEER:" at 10903.5,-1369.5 h45
  text "LAYOUT BY:" at 12408.5,-1369.5 h45
  text "or any information contained therein. TI and/or its licensors do not warrant that this design will meet" at 5889.01,-1474 h45
  text ".PRJ_Engineer" at 10953.5,-1524.49 h70
  text ".PCB_Layout" at 12459,-1524.49 h70
  text "the specifications, will be suitable for your application or fit for any particular purpose, or will operate in" at 5889.01,-1586.67 h45
  text "ALTIUM DESIGNER VERSION:" at 12408.5,-1679.5 h45
  text "an implementation. TI and/or its licensors do not warrant that the design is production worthy. You should" at 5889.01,-1699.33 h45
  text "completely validate and test your design implementation to confirm the system functionality for your application." at 5934,-1812 h45
  text ".print_Scale" at 10953.5,-1812.83 h70
  text ".Application_BuildNumber" at 12459,-1812.83 h70
  text "2" at 2795.5,-2019.5 h70
  text "3" at 5284.84,-2019.5 h70
  text "4" at 7791.51,-2019.5 h70
  text "5" at 10290.5,-2019.5 h70
  text "6" at 12795.5,-2019.5 h70
M10 Fab Notes:
  drawing of 228 lines, arcs and shapes, not listed
  text "DESIGN INFORMATION" at 11941.02,6054 h60
  text "(REFER ALSO ARRAY/PANEL PROFILING INFORMATION)" at 11579.46,5892.29 h60
  text "BOARD SIZE" at 10893.46,5888 h60
  text "95MM" at 11355.78,5760.18 h60
  text "X" at 11861.46,5760.18 h60
  text "135MM" at 12092.78,5760.18 h60
  text "Number of Layers :" at 11296.46,5563 h60
  text "4" at 12391.27,5553 h60
  text "MIN. TRACK WIDTH:" at 11296.46,5424 h60
  text "10" at 12392.7,5424 h60
  text "MIL" at 12547.46,5424 h60
  text "8" at 12395,5300 h60
  text "MIN. CLEARANCE:" at 11296.46,5292 h60
  text "MIL" at 12547.46,5292 h60
  text "7.874" at 12240,5165 h60
  text "MIN. VIA DRILL SIZE:" at 11296.46,5160 h60
  text "MIL" at 12547.46,5160 h60
  text "5.9055 MIL" at 11991.46,5018.29 h60
  text "MINIMUM ANNULAR RING" at 10967.23,5014.01 h60
  text "EXTERNAL" at 12699.46,5014.01 h60
  text "PER" at 11167.23,4896 h60
  text "IPC-D-275 CLASS 2 LEVEL C" at 11387.23,4896 h60
  text "MIL, HOLES" at 12875.46,4783.71 h60
  text "+/-" at 12483,4783 h60
  text "+/-" at 13337,4783 h60
  text "REGISTRATION TOLERANCES:" at 10967.23,4778 h60
  text "METAL" at 12167,4778 h60
  text "5" at 12743.2,4778 h60
  text "3" at 13576.2,4778 h60
  text "MIL" at 13692.46,4778 h60
  text "MATERIAL:" at 10892.46,4568.54 h60
  text "FR-4 High Tg" at 11878.9,4428.21 h60
  text "FR-408" at 11313.46,4419.64 h60
  text "X" at 11720,4420 h60
  text "OTHER" at 12801.46,4419.64 h60
  text "63 MIL (1.6mm) +/-10%" at 11633.56,4256.92 h60
  text "THICKNESS:" at 10967.23,4252.64 h60
  text "X" at 11505.4,4252.64 h60
  text "OTHER" at 12918.46,4252.64 h60
  text "TOLERANCE:" at 10967.23,4094.64 h60
  text "X" at 11806.53,4094.64 h60
  text "ANSI IPC-6012 TYPE 3 CLASS 2" at 11993.48,4094.64 h60
  text "OTHER +/-" at 11993.46,3938.64 h60
  text "BOW & TWIST:" at 10967.23,3781.64 h60
  text "X" at 11806.53,3781.64 h60
  text "ANSI IPC-6012 TYPE 3 CLASS 2" at 11993.48,3781.64 h60
  text "OTHER +/-" at 11993.46,3623.13 h60
  text "COPPER THICKNESS (FINISHED):" at 10892.46,3487.64 h60
  text "1.4MIL (1oz)" at 11772.46,3334.92 h60
  text "2MIL (1.4oz)" at 12539.46,3334.92 h60
  text "X" at 13145,3335 h60
  text "2.8MIL (2oz)" at 13266.46,3334.92 h60
  text "OUTER:" at 11249.46,3330.64 h60
  text "X" at 11644,3185 h60
  text "1.4MIL (1oz)" at 11772.46,3177.92 h60
  text "2.8MIL (2oz)" at 12539.46,3177.92 h60
  text "N/A" at 13266,3178.29 h60
  text "INNER SIGNAL:" at 10960.38,3173.64 h60
  text "DRILLING:" at 10892.46,3034.64 h60
  text "REFERENCE:" at 10967.23,2917.64 h60
  text "X" at 11615.46,2917.64 h60
  text "AS SHOWN" at 11802.46,2917.64 h60
  text "X" at 12516.46,2917.64 h60
  text "NC_DRILL FILES" at 12653.46,2917.64 h60
  text "PTH MIN COPPER THICKNESS:" at 10967.23,2759.64 h60
  text "X" at 12317.46,2759.64 h60
  text "1MIL" at 12454.46,2759.64 h60
  text "OTHER" at 12951.46,2759.64 h60
  text "BOARD FINISH:" at 10892.46,2600.64 h60
  text "SILKSCREEN:" at 11047.68,2482.64 h60
  text "X" at 11996.46,2482.64 h60
  text "TOP" at 12122.46,2482.64 h60
  text "X" at 12506.46,2482.64 h60
  text "BOTTOM" at 12633.46,2482.64 h60
  text "SILKSCREEN COLOR:" at 11047.68,2315.64 h60
  text "X" at 11995.42,2315.64 h60
  text "WHITE" at 12122.46,2315.64 h60
  text "OTHER" at 12633.46,2315.64 h60
  text "SOLDER RESIST COLOR:" at 11047.68,2145.64 h60
  text "X" at 11615.42,1986.44 h60
  text "GREEN" at 11742.46,1986.44 h60
  text "BLUE" at 12333.46,1986.44 h60
  text "OTHER" at 12871.46,1986.44 h60
  text "IMMERSION GOLD (ENIG)" at 11953.46,1797.92 h60
  text "ENEPIG" at 13291,1794.64 h60
  text "SURFACE FINISH:" at 10892.46,1793.64 h60
  text "X" at 11766.51,1793.64 h60
  text "IMM. TIN/SILVER OR EQUIV" at 11222,1636.64 h60
  text "OTHER" at 12653.46,1636.64 h60
  text "ARRAY/PANEL:" at 10892.46,1457.64 h60
  text "CUT AND TRIM PER MECH LAYER 1" at 11953.46,1453.35 h60
  text "N.C. ROUTE" at 11953.46,1301.64 h60
  text "X" at 12632.46,1301.64 h60
  text "V. SCORE" at 12819.46,1301.64 h60
  text "CERTIFICATION:" at 10892.46,1164.64 h60
  text "MATERIALS AND WORKMANSHIP FOR ALL PCBS" at 11617.46,1164.64 h60
  text "TO MEET OR EXCEED THE REQUIREMENTS OF:" at 11617.46,1066.64 h60
  text "X" at 11243.96,930.14 h60
  text "ANSI IPC-A-600F CLASS ->" at 11382.96,930.14 h60
  text "X" at 13022.02,930.14 h60
  text "2" at 13140.96,930.14 h60
  text "1" at 12825.96,928.64 h60
  text "3" at 13494.96,928.64 h60
  text "X" at 11246.02,770.64 h60
  text "UL 94V-0" at 11382.96,770.64 h60
  text "X" at 12058.02,770.64 h60
  text "RoHS" at 12194.96,770.64 h60
  text "OTHER" at 12839.36,770.64 h60
  text "PER ORDER" at 13236.42,770.64 h60
  text "VIA TENTING:" at 12110,637 h60
  text "X" at 13190,635 h60
  text "ADDITIONAL REQUIREMENTS:" at 10892.46,629.64 h60
  text "YES" at 12659.67,627.92 h60
  text "NO" at 13024.47,622.69 h60
  text "MICROSECTION:" at 10967.23,514.64 h60
  text "YES" at 11872.96,514.64 h60
  text "IMPEDANCE CONTROL:" at 12132,508 h60
  text "YES" at 13116,507 h60
  text "X" at 13658,500 h60
  text "NO" at 13491.47,489.69 h60
  text "REQUIRED" at 12734.46,358.5 h60
  text "BARE BOARD ELEC. TEST:" at 10967.23,355.64 h60
  text "NONE" at 12272.96,355.64 h60
  text "X" at 12607.46,355.64 h60
  text "PER ORDER" at 13326.46,355.64 h60
  text "MANUFACTURER'S UL:" at 10967.23,198.64 h60
  text "RAIL" at 12132.96,194.35 h60
  text "METAL" at 12624.77,194.35 h60
  text "X" at 13000,194 h60
  text "SILK" at 13136.46,194.35 h60
M11 Gerber Information:
  lines w10: -732,-1686.17 5868,-1686.17 ; -732,-1482.83 5870,-1482.83 ; -732,-1279.5 -732,-1889.5 3273,-1889.5 5870,-1889.5 5870,-1279.5 -731.5,-1279.5 -731.5,-1889.5 ; 1733,-1889.5 1733,-1279.5 ; 3000,-1482.83 3000,-1279.5 ; 3840,-1482.83 3840,-1279.5 ; 4462,-1896 4462,-1693.17
  text "BOARD #:" at 1808,-1411.67 h60
  text ".PRJ_Number" at 2353.5,-1411.67 h60
  text "REV:" at 3198,-1411.67 h60
  text ".PCB_Rev" at 3489.5,-1411.67 h60
  text "SVN REV:" at 4036,-1411.67 h60
  text ".VersionControl_RevNumber" at 4542,-1411.67 h60
  text "ALL ARTWORK VIEWED FROM TOP SIDE" at -669.5,-1417.67 h60
  text "LAYER NAME =" at -671,-1601 h60
  text ".plot_File_Name" at -679,-1800 h60
  text "GENERATED    :" at 1810,-1820.34 h60
  text ".Print_Date" at 2679.5,-1820.34 h60
  text ".Print_Time" at 3408.5,-1820.34 h60
  text "TEXAS INSTRUMENTS" at 4673,-1820.34 h60
M12 Stackup:
  lines w6: 10920,6704 13470,6704 ; 10920,6808.4 13470,6808.4 ; 10860,6219 ccw(c10894,6219) 10894,6185 13496,6185 ccw(c13496,6219) 13530,6219 13530,6925 ccw(c13496,6925) 13496,6959 10894,6959 ccw(c10894,6925) 10860,6925 10860,6219
  text "Layer Stack Up Detail for: TIDA-00905-E1" at 10920,6841.1 h57
  text "Layer" at 10920,6769.4 h24
  text "Gerber" at 11815.81,6769.4 h24
  text "Copper" at 12379.33,6769.4 h24
  text "Dielectric" at 12982.04,6769.4 h24
  text "Name" at 10920,6721.4 h24
  text "Document" at 11815.81,6721.4 h24
  text "Thickness" at 12379.33,6721.4 h24
  text "Material" at 12982.04,6721.4 h24
  text "Top Solder Mask" at 10935,6630 h34
  text "(.GTS)" at 11815.81,6628.44 h34
  text "Solder Resist" at 12982.04,6628.44 h34
  text "Top Layer" at 10930,6535 h34
  text "(.GTL)" at 11815.81,6531.69 h34
  text "2.8mil" at 12379.33,6531.69 h34
  text "FR4-High Tg" at 13011,6531 h34
  text "FR4-High Tg" at 13016,6476 h34
  text "1.4mil" at 12379.33,6466.69 h34
  text "GND" at 10929,6463 h34
  text "(.G1)" at 11814.81,6454.69 h34
  text "FR4-High Tg" at 13016,6401 h34
  text "1.4mil" at 12379.33,6396.69 h34
  text "(.G2)" at 11814.81,6384.69 h34
  text "PWR" at 10929,6383 h34
  text "FR4-High Tg" at 13016,6306 h34
  text "Bottom Layer" at 10925,6305 h34
  text "(.GBL)" at 11824,6301 h34
  text "2.8mil" at 12384,6295 h34
  text "Solder Resist" at 12976,6228 h34
  text "(.GBS)" at 11821,6221 h34
  text "Bottom Solder Mask" at 10930,6220 h34
M13 Component Bodies Top:
  text ".Layer_Name" at 137,-1614.49 h60
M14 Component Bodies Bottom:
  text ".Layer_Name" at 137,-1614.49 h60
M15 Courtyards Top:
  text ".Layer_Name" at 137,-1614.49 h60
M16 Courtyards Bottom:
  text ".Layer_Name" at 137,-1614.49 h60
Drill Drawing:
  text ".legend" at 3997,1997 h60
  text "Drill Table" at 3994,1826 h60
  text "FOR 12MIL DRILL +0/-12MIL" at 4022,1620 h60
  text "FOR 7.874MIL DRILL +0/-7.874MIL" at 4020,1516 h60
  text "FOR 16MIL DRILL +0/-16MIL" at 4021,1412 h60
  text "FOR PTH DRILL +/-3MIL" at 4021,1294 h60
  text "FOR NPTH DRILL +/-2MIL" at 4031,1194 h60
  text ".layer_Name" at 242,-1598 h60

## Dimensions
0,0 to 3740.15,0 on M2 Board Dimensions
0,0 to 0,5314.95 on M2 Board Dimensions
